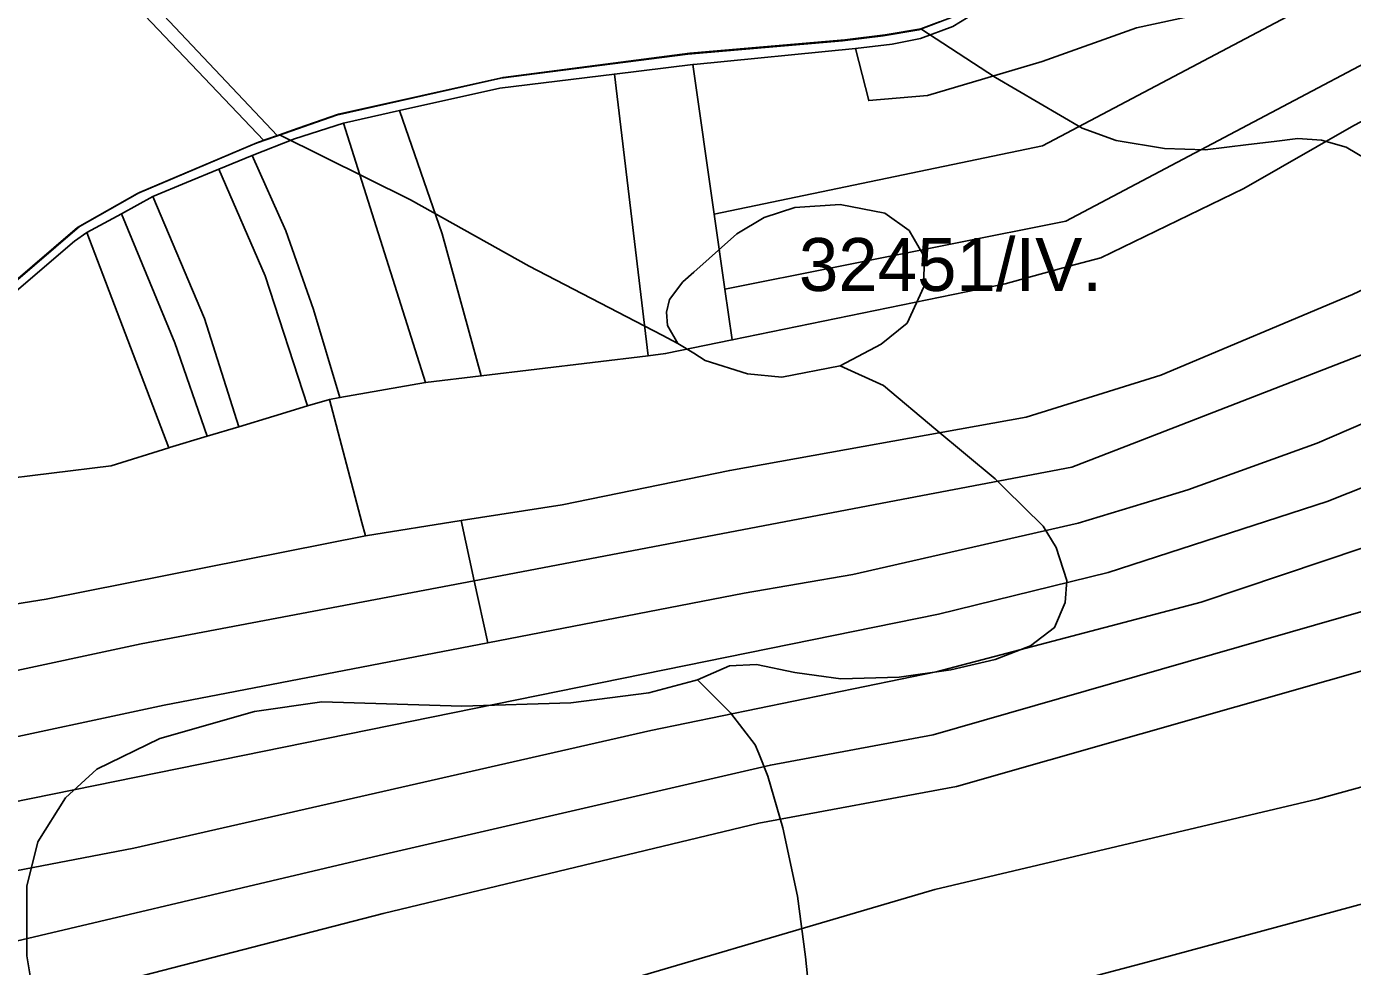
# Model space of a CAD drawing. Extents: x -535894 to -532827, y -1165802 to -1163635.
# Drawn here: x -535189 to -534813.3, y -1164827.4 to -1164561.1 of the extents above; entities that cross this region are included whole.
import ezdxf

# ---------------------------------------------------------------- set-up
doc = ezdxf.new("R2010")
doc.units = 0
for name, color, linetype in [('BPEJ_s', 7, 'Continuous'), ('orna_s', 7, 'Continuous'), ('ostatni_s', 7, 'Continuous'), ('PUPFL_s', 7, 'Continuous')]:
    doc.layers.add(name, color=color, linetype=linetype)

msp = doc.modelspace()

# ---------------------------------------------------------------- linework, layer by layer
at = {"layer": 'BPEJ_s'}
for points in [[(-534930.369, -1164559.695), (-534935.616, -1164561.701), (-534945.728, -1164563.423), (-534957.21, -1164564.802), (-535000, -1164568.532), (-535001.057, -1164568.625), (-535054.023, -1164575.458), (-535100.616, -1164585.868), (-535112.034, -1164589.882), (-535117.371, -1164591.759), (-535121.179, -1164593.097), (-535123.817, -1164594.021), (-535156.991, -1164608.077), (-535174.047, -1164617.688), (-535225.782, -1164662.124), (-535264.558, -1164694.259), (-535273.775, -1164699.521), (-535285.222, -1164705.064), (-535292.152, -1164708.42), (-535298.828, -1164711.653), (-535321.651, -1164717.756), (-535337.207, -1164722.574), (-535394.549, -1164753.205), (-535432.662, -1164773.563)], [(-534987.81, -1164619.8), (-535000.001, -1164630.658), (-535003.1, -1164633.42), (-535006.837, -1164638.361), (-535007.72, -1164642.02), (-535007.4, -1164645.77), (-535004.53, -1164650.86), (-535008.91, -1164648.51), (-535046.58, -1164628.92), (-535080.19, -1164610.13), (-535117.371, -1164591.759), (-535112.034, -1164589.882), (-535100.616, -1164585.868), (-535054.023, -1164575.458), (-535001.057, -1164568.625), (-535000, -1164568.532), (-534957.21, -1164564.802), (-534945.728, -1164563.423), (-534935.616, -1164561.701), (-534914.46, -1164575.48), (-534889.93, -1164589.82), (-534880.29, -1164593.32), (-534866.6, -1164595.63), (-534855.05, -1164596.03), (-534842.78, -1164594.52), (-534835.54, -1164593.629), (-534828.79, -1164592.798), (-534822.08, -1164593.24), (-534815.11, -1164595.27), (-534809.571, -1164598.54)], [(-534790.62, -1164617.29), (-534803.2, -1164604.15), (-534809.571, -1164598.54), (-534815.11, -1164595.27), (-534822.08, -1164593.24), (-534828.79, -1164592.798), (-534835.54, -1164593.629), (-534842.78, -1164594.52), (-534855.05, -1164596.03), (-534866.6, -1164595.63), (-534880.29, -1164593.32), (-534889.93, -1164589.82), (-534914.46, -1164575.48), (-534935.616, -1164561.701), (-534930.369, -1164559.695)], [(-535225.782, -1164662.124), (-535174.047, -1164617.688), (-535156.991, -1164608.077), (-535123.817, -1164594.021), (-535121.179, -1164593.097), (-535117.371, -1164591.759), (-535080.19, -1164610.13), (-535046.58, -1164628.92), (-535008.91, -1164648.51), (-535004.53, -1164650.86)], [(-534964.71, -1164859.4), (-534968.3, -1164824.6), (-534970.61, -1164807.39), (-534974.75, -1164788.119), (-534978.97, -1164773.39), (-534981.555, -1164767.006), (-534982.55, -1164764.55), (-534989.56, -1164755.47), (-534998.88, -1164746.15), (-534989.88, -1164742.17), (-534982.23, -1164741.77), (-534971.32, -1164744.08), (-534965.241, -1164744.9), (-534958.34, -1164745.83), (-534941.78, -1164745.43), (-534927.119, -1164743.28), (-534914.62, -1164740.34), (-534904.579, -1164736.52), (-534897.74, -1164731.34), (-534894.71, -1164724.25), (-534894.31, -1164718.04), (-534897.26, -1164708.64), (-534901, -1164702.59), (-534911.817, -1164691.901), (-534914.54, -1164689.21), (-534931.42, -1164675.19), (-534946.24, -1164662.77), (-534958.5, -1164657.23), (-534946.87, -1164651.02), (-534939.55, -1164645.13), (-534934.767, -1164634.758), (-534934.723, -1164626.253), (-534938.91, -1164618.851), (-534945.817, -1164613.887), (-534958.5, -1164611.52), (-534971.375, -1164612.361), (-534980, -1164615.18), (-534987.81, -1164619.8)], [(-535004.53, -1164650.86), (-535000, -1164653.636), (-534996.73, -1164655.64), (-534984.78, -1164659.461), (-534975.07, -1164660.42), (-534958.5, -1164657.23), (-534946.24, -1164662.77), (-534931.42, -1164675.19), (-534914.54, -1164689.21), (-534911.817, -1164691.901), (-534901, -1164702.59), (-534897.26, -1164708.64), (-534894.31, -1164718.04), (-534894.71, -1164724.25), (-534897.74, -1164731.34), (-534904.579, -1164736.52), (-534914.62, -1164740.34), (-534927.119, -1164743.28), (-534941.78, -1164745.43), (-534958.34, -1164745.83), (-534965.241, -1164744.9), (-534971.32, -1164744.08), (-534982.23, -1164741.77), (-534989.88, -1164742.17), (-534998.88, -1164746.15), (-535000.001, -1164746.447), (-535012.66, -1164749.811), (-535034.79, -1164752.68), (-535065.7, -1164753.639), (-535105.36, -1164752.36), (-535124.47, -1164755.07), (-535151.23, -1164762.72), (-535169.07, -1164771.48), (-535177.99, -1164779.6), (-535185.79, -1164792.02), (-535188.98, -1164804.61), (-535188.98, -1164824.36), (-535186.43, -1164839.65)], [(-535186.43, -1164839.65), (-535188.98, -1164824.36), (-535188.98, -1164804.61), (-535185.79, -1164792.02), (-535177.99, -1164779.6), (-535169.07, -1164771.48), (-535151.23, -1164762.72), (-535124.47, -1164755.07), (-535105.36, -1164752.36), (-535065.7, -1164753.639), (-535034.79, -1164752.68), (-535012.66, -1164749.811), (-535000.001, -1164746.447), (-534998.88, -1164746.15), (-534989.56, -1164755.47), (-534982.55, -1164764.55), (-534981.555, -1164767.006), (-534978.97, -1164773.39), (-534974.75, -1164788.119), (-534970.61, -1164807.39), (-534968.3, -1164824.6), (-534964.71, -1164859.4)]]:
    msp.add_lwpolyline(points, dxfattribs=at)
msp.add_lwpolyline([(-534958.5, -1164657.23), (-534975.07, -1164660.42), (-534984.78, -1164659.461), (-534996.73, -1164655.64), (-535000, -1164653.636), (-535004.53, -1164650.86), (-535007.4, -1164645.77), (-535007.72, -1164642.02), (-535006.837, -1164638.361), (-535003.1, -1164633.42), (-535000.001, -1164630.658), (-534987.81, -1164619.8), (-534980, -1164615.18), (-534971.375, -1164612.361), (-534958.5, -1164611.52), (-534945.817, -1164613.887), (-534938.91, -1164618.851), (-534934.723, -1164626.253), (-534934.767, -1164634.758), (-534939.55, -1164645.13), (-534946.87, -1164651.02)], close=True, dxfattribs=at)
at = {"layer": 'orna_s'}
for points in [[(-534836.85, -1164503.64), (-534832.14, -1164532.75), (-534822.67, -1164545.3), (-534830, -1164550.13), (-534845.17, -1164555.12), (-534874.58, -1164561.46), (-534901.23, -1164570.96), (-534933.74, -1164580.6), (-534950.39, -1164582.04), (-534954.11, -1164567.3), (-534943.8, -1164566.05), (-534935.73, -1164564.46), (-534926.58, -1164561.08), (-534915.74, -1164554.41), (-534905.82, -1164546.8), (-534892.07, -1164534.38)], [(-534768.01, -1164509.35), (-534755.68, -1164518.03), (-534901.21, -1164594.89), (-534994.2, -1164614.17), (-535000.27, -1164571.83), (-534999.95, -1164571.8), (-534954.11, -1164567.3), (-534950.39, -1164582.04), (-534933.74, -1164580.6), (-534901.23, -1164570.96), (-534874.58, -1164561.46), (-534845.17, -1164555.12), (-534830, -1164550.13), (-534822.67, -1164545.3)], [(-534755.68, -1164518.03), (-534749.42, -1164524.99), (-534743.38, -1164536.18), (-534894.51, -1164616.18), (-534991.15, -1164635.45), (-534994.2, -1164614.17), (-534901.21, -1164594.89)], [(-534743.38, -1164536.18), (-534737.42, -1164549.39), (-534812.95, -1164589.11), (-534844.16, -1164606.93), (-534884.64, -1164626.55), (-534893.57, -1164628.99), (-534911.75, -1164633.96), (-534989.09, -1164649.85), (-534991.15, -1164635.45), (-534894.51, -1164616.18)], [(-535000.27, -1164571.83), (-534994.2, -1164614.17), (-534991.15, -1164635.45), (-534989.09, -1164649.85), (-535007.94, -1164653.73), (-535012.94, -1164654.33), (-535022.48, -1164574.53)], [(-535022.48, -1164574.53), (-535012.94, -1164654.33), (-535060.19, -1164660.03), (-535071.3, -1164619.75), (-535083.39, -1164584.89), (-535054.91, -1164578.48)], [(-535083.39, -1164584.89), (-535071.3, -1164619.75), (-535060.19, -1164660.03), (-535075.97, -1164661.94), (-535099.23, -1164588.45)], [(-535099.23, -1164588.45), (-535075.97, -1164661.94), (-535100.22, -1164666.18), (-535107.76, -1164641.26), (-535115.56, -1164618.94), (-535125.13, -1164597.55), (-535113.13, -1164592.91)], [(-534710.3, -1164588.31), (-534700.55, -1164604.45), (-534706.29, -1164606.67), (-534778.34, -1164641.2), (-534797.89, -1164649.09), (-534877.44, -1164679.92), (-534892.83, -1164685.88), (-534939.12, -1164694.71), (-535062.16, -1164718.07), (-535065.86, -1164701.05), (-535037.23, -1164696.56), (-534989.77, -1164686.82), (-534905.84, -1164671.7), (-534882.51, -1164664.49), (-534867.62, -1164659.87), (-534813.38, -1164637)], [(-535125.13, -1164597.55), (-535115.56, -1164618.94), (-535107.76, -1164641.26), (-535100.22, -1164666.18), (-535103.22, -1164666.7), (-535109.38, -1164668.56), (-535121.44, -1164631.71), (-535134.56, -1164601.46)], [(-535134.56, -1164601.46), (-535121.44, -1164631.71), (-535109.38, -1164668.56), (-535118.94, -1164671.44), (-535128.9, -1164674.44), (-535138.58, -1164643.8), (-535153.21, -1164609.19), (-535143.69, -1164605.24)], [(-534706.29, -1164606.67), (-534700.55, -1164604.45), (-534690.65, -1164624.3), (-534694.91, -1164625.88), (-534731.01, -1164639.29), (-534823.37, -1164679.09), (-534859.96, -1164692.33), (-534872.36, -1164696.09), (-534891.05, -1164701.75), (-534954.93, -1164716.28), (-534985.67, -1164721.59), (-535058.34, -1164735.63), (-535062.16, -1164718.07), (-534939.12, -1164694.71), (-534892.83, -1164685.88), (-534877.44, -1164679.92), (-534797.89, -1164649.09), (-534778.34, -1164641.2)], [(-535153.21, -1164609.19), (-535138.58, -1164643.8), (-535128.9, -1164674.44), (-535137.84, -1164677.14), (-535147.02, -1164650.67), (-535162.09, -1164614.13)], [(-535162.09, -1164614.13), (-535147.02, -1164650.67), (-535137.84, -1164677.14), (-535148.51, -1164680.35), (-535148.68, -1164680.4), (-535171.93, -1164619.38)], [(-535171.93, -1164619.38), (-535148.68, -1164680.4), (-535165.07, -1164685.54), (-535198.96, -1164689.65), (-535214.35, -1164655.15), (-535175.47, -1164621.86)], [(-534690.65, -1164624.3), (-534680.75, -1164641.94), (-534685.32, -1164643.53), (-534716.28, -1164654.24), (-534820.53, -1164695.61), (-534882.6, -1164715.73), (-534930.6, -1164727.52), (-535229.64, -1164788.31), (-535234.09, -1164770.13), (-535204.83, -1164765.01), (-535150, -1164753.33), (-535058.34, -1164735.63), (-534985.67, -1164721.59), (-534954.93, -1164716.28), (-534891.05, -1164701.75), (-534872.36, -1164696.09), (-534859.96, -1164692.33), (-534823.37, -1164679.09), (-534731.01, -1164639.29), (-534694.91, -1164625.88)], [(-534685.32, -1164643.53), (-534680.75, -1164641.94), (-534669.21, -1164659.89), (-534675.43, -1164661.72), (-534705.37, -1164670.56), (-534787.37, -1164701.01), (-534856.21, -1164724.15), (-534931.28, -1164743.9), (-535012.13, -1164760.48), (-535158.6, -1164793.79), (-535225.1, -1164806.57), (-535229.64, -1164788.31), (-534930.6, -1164727.52), (-534882.6, -1164715.73), (-534820.53, -1164695.61), (-534716.28, -1164654.24)], [(-534669.21, -1164659.89), (-534657.84, -1164675.77), (-534662.44, -1164677.22), (-534691.34, -1164686.36), (-534795.22, -1164722.3), (-534932.16, -1164761.71), (-534978.25, -1164770.31), (-535087.47, -1164795.57), (-535217.32, -1164826.11), (-535225.1, -1164806.57), (-535158.6, -1164793.79), (-535012.13, -1164760.48), (-534931.28, -1164743.9), (-534856.21, -1164724.15), (-534787.37, -1164701.01), (-534705.37, -1164670.56), (-534675.43, -1164661.72)], [(-535109.38, -1164668.56), (-535103.22, -1164666.7), (-535094.01, -1164701.59), (-535093.03, -1164705.31), (-535183.44, -1164723.28), (-535249.16, -1164733.82), (-535257.9, -1164704.48), (-535226.15, -1164694.74), (-535198.96, -1164689.65), (-535165.07, -1164685.54), (-535148.68, -1164680.4), (-535148.51, -1164680.35), (-535137.84, -1164677.14), (-535128.9, -1164674.44), (-535118.94, -1164671.44)], [(-534662.44, -1164677.22), (-534657.84, -1164675.77), (-534648.21, -1164691.35), (-534794.04, -1164738.9), (-534925.58, -1164776.38), (-534981.55, -1164786.79), (-535087.94, -1164812.37), (-535210.21, -1164843.9), (-535217.32, -1164826.11), (-535087.47, -1164795.57), (-534978.25, -1164770.31), (-534932.16, -1164761.71), (-534795.22, -1164722.3), (-534691.34, -1164686.36)], [(-534644.26, -1164706.72), (-534642.29, -1164732.8), (-534729.01, -1164753.95), (-534823.37, -1164779.94), (-534931.7, -1164805.53), (-535046.65, -1164839.34), (-535194.99, -1164879.49), (-535210.21, -1164843.9), (-535087.94, -1164812.37), (-534981.55, -1164786.79), (-534925.58, -1164776.38), (-534794.04, -1164738.9), (-534648.21, -1164691.35)], [(-535065.86, -1164701.05), (-535062.16, -1164718.07), (-535156.56, -1164735.99), (-535198.52, -1164744.91), (-535241.65, -1164751.91), (-535249.16, -1164733.82), (-535183.44, -1164723.28), (-535093.03, -1164705.31)], [(-535062.16, -1164718.07), (-535058.34, -1164735.63), (-535150, -1164753.33), (-535204.83, -1164765.01), (-535234.09, -1164770.13), (-535241.65, -1164751.91), (-535198.52, -1164744.91), (-535156.56, -1164735.99)], [(-534729.01, -1164753.95), (-534642.29, -1164732.8), (-534639.25, -1164772.83), (-534705.71, -1164784.93), (-534805.56, -1164808.33), (-534871.85, -1164826.25), (-534989.4, -1164857.3), (-535007.79, -1164862.16), (-535095.84, -1164891.7), (-535170.48, -1164913.86), (-535177.9, -1164919.08), (-535185.4, -1164901.91), (-535194.99, -1164879.49), (-535046.65, -1164839.34), (-534931.7, -1164805.53), (-534823.37, -1164779.94)], [(-534639.25, -1164772.83), (-534637.67, -1164793.79), (-534635.77, -1164799.17), (-534633.72, -1164804.95), (-534638.54, -1164823.25), (-534671.88, -1164825.83), (-534710.47, -1164830.87), (-534729.94, -1164834.28), (-534841.03, -1164853.81), (-534900.4, -1164867.67), (-534930.69, -1164876.79), (-534980.06, -1164892.73), (-535115.81, -1164936.57), (-535159.15, -1164946.66), (-535170.48, -1164913.86), (-535095.84, -1164891.7), (-535007.79, -1164862.16), (-534989.4, -1164857.3), (-534871.85, -1164826.25), (-534805.56, -1164808.33), (-534705.71, -1164784.93)]]:
    msp.add_lwpolyline(points, close=True, dxfattribs=at)
msp.add_lwpolyline([(-534710.3, -1164588.31), (-534813.38, -1164637), (-534867.62, -1164659.87), (-534882.51, -1164664.49), (-534905.84, -1164671.7), (-534989.77, -1164686.82), (-535037.23, -1164696.56), (-535065.86, -1164701.05), (-535093.03, -1164705.31), (-535094.01, -1164701.59), (-535103.22, -1164666.7), (-535100.22, -1164666.18), (-535075.97, -1164661.94), (-535060.19, -1164660.03), (-535012.94, -1164654.33), (-535007.94, -1164653.73), (-534989.09, -1164649.85), (-534911.75, -1164633.96), (-534893.57, -1164628.99), (-534884.64, -1164626.55), (-534844.16, -1164606.93), (-534812.95, -1164589.11)], dxfattribs=at)
at = {"layer": 'ostatni_s'}
for points in [[(-534915.74, -1164554.41), (-534926.58, -1164561.08), (-534935.73, -1164564.46), (-534943.8, -1164566.05), (-534954.11, -1164567.3), (-534999.95, -1164571.8), (-535000.27, -1164571.83), (-535022.48, -1164574.53), (-535054.91, -1164578.48), (-535083.39, -1164584.89), (-535099.23, -1164588.45), (-535113.13, -1164592.91), (-535125.13, -1164597.55), (-535134.56, -1164601.46), (-535143.69, -1164605.24), (-535153.21, -1164609.19), (-535162.09, -1164614.13), (-535171.93, -1164619.38), (-535175.47, -1164621.86), (-535214.35, -1164655.15)], [(-535226.37, -1164662.4), (-535174.63, -1164617.97), (-535157.57, -1164608.35), (-535124.4, -1164594.3), (-535121.76, -1164593.37), (-535117.95, -1164592.03), (-535101.2, -1164586.14), (-535054.61, -1164575.73), (-535001.64, -1164568.89), (-534957.79, -1164565.07), (-534946.31, -1164563.69), (-534936.2, -1164561.96), (-534926.03, -1164558.08)]]:
    msp.add_lwpolyline(points, dxfattribs=at)
at = {"layer": 'PUPFL_s'}
for points in [[(-535644.3, -1164037.06), (-535329.29, -1164368.36), (-535086.95, -1164143.16), (-535085.71, -1164144.07), (-535085.14, -1164146.96), (-535326.28, -1164371.53), (-535117.95, -1164592.03), (-535121.76, -1164593.37), (-535329.84, -1164374.82), (-535605.04, -1164629.61), (-535608.87, -1164626.28), (-535332.86, -1164371.64), (-535474.5, -1164222.2), (-535476.52, -1164220.08), (-535649.36, -1164037.73)], [(-535121.76, -1164593.37), (-535124.4, -1164594.3), (-535157.57, -1164608.35), (-535174.63, -1164617.97), (-535226.37, -1164662.4), (-535265.14, -1164694.54), (-535274.36, -1164699.8), (-535299.42, -1164711.94), (-535322.24, -1164718.04), (-535337.8, -1164722.86), (-535434.81, -1164774.69), (-535538.55, -1164687.07), (-535605.04, -1164629.61), (-535329.84, -1164374.82)]]:
    msp.add_lwpolyline(points, close=True, dxfattribs=at)
msp.add_lwpolyline([(-534926.03, -1164558.08), (-534936.2, -1164561.96), (-534946.31, -1164563.69), (-534957.79, -1164565.07), (-535001.64, -1164568.89), (-535054.61, -1164575.73), (-535101.2, -1164586.14), (-535117.95, -1164592.03), (-535326.28, -1164371.53)], dxfattribs=at)

# ---------------------------------------------------------------- texts
at = {"layer": 'BPEJ_s'}
msp.add_text('32451/IV.', height=15, dxfattribs=at).set_placement((-534970.177, -1164635.97))

doc.saveas('drawing.dxf')
